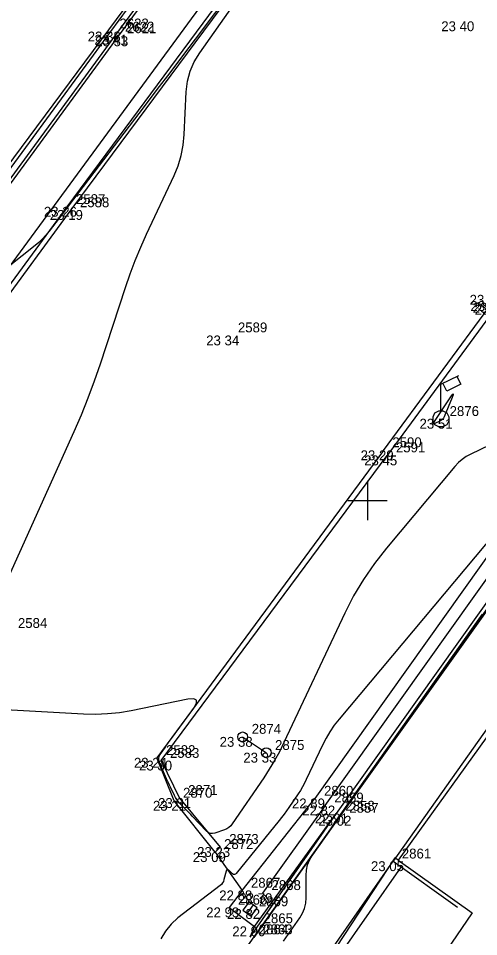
# Model space of a CAD drawing. Extents: x -702257 to -701487, y -1009871 to -1008841.
# Drawn here: x -701883.84 to -701872.19, y -1009561.05 to -1009537.78 of the extents above; entities that cross this region are included whole.
import ezdxf

# ---------------------------------------------------------------- set-up
doc = ezdxf.new("R2010")
doc.units = 0
for name, color, linetype in [('Ex_Major Contours', 7, 'Continuous'), ('Ex_Minor Contours', 7, 'Continuous'), ('Z_body', 7, 'Continuous'), ('Z_body_cisla', 7, 'Continuous'), ('Z_body_vysky_redukovane', 7, 'Continuous'), ('Z_budova', 7, 'Continuous'), ('Z_hektometricka_sit', 7, 'Continuous'), ('Z_katastr_hranice', 7, 'Continuous'), ('Z_katastr_vnitrni_kresba', 7, 'Continuous'), ('Z_komunikace', 7, 'Continuous'), ('Z_nastenka', 7, 'Continuous'), ('Z_obruba', 7, 'Continuous'), ('Z_ploty', 7, 'Continuous'), ('Z_rozhranni', 7, 'Continuous'), ('Z_site_kanalizace_znaky', 7, 'Continuous'), ('Z_site_vo_znaky', 7, 'Continuous'), ('Z_zlabek', 7, 'Continuous')]:
    doc.layers.add(name, color=color, linetype=linetype)

# ---------------------------------------------------------------- blocks, each defined once
blk = doc.blocks.new('POINT_DISPLAY')
blk.add_line((0, 0), (0, 0))
blk = doc.blocks.new('Z46260')
for p, q in [((0.13, 0.13), (-0.13, 0.13)), ((-0.13, 0.13), (-0.13, -0.13)), ((0.13, 0), (-0.13, 0)), ((0.13, -0.13), (0.13, 0.13)), ((-0.13, -0.13), (0.13, -0.13))]:
    blk.add_line(p, q)
blk = doc.blocks.new('Z13')
for p, q in [((0, 0.88), (0.45, 1.1)), ((0.4, 1.07), (0.5, 0.88)), ((0, 0.2), (0, 0.88)), ((0.15, 0.7), (0.05, 0.9)), ((0.5, 0.88), (0.15, 0.7)), ((-0.2, 0.05), (-0.15, 0.15)), ((-0.2, -0.05), (-0.2, 0.05)), ((-0.15, 0.15), (-0.05, 0.2)), ((-0.05, 0.2), (0.05, 0.2)), ((0.05, 0.2), (0.15, 0.15)), ((0.15, 0.15), (0.2, 0.05)), ((0.2, 0.05), (0.2, -0.05)), ((-0.15, -0.15), (-0.2, -0.05)), ((-0.05, -0.2), (-0.15, -0.15)), ((0.05, -0.2), (-0.05, -0.2)), ((0.15, -0.15), (0.05, -0.2)), ((0.2, -0.05), (0.15, -0.15))]:
    blk.add_line(p, q)
blk = doc.blocks.new('Z15')
blk.add_circle((0, 0), 0.125)

msp = doc.modelspace()

# ---------------------------------------------------------------- linework, layer by layer
at = {"layer": 'Ex_Major Contours'}
for points in [[(-701870.663, -1009549.499), (-701875.719, -1009555.543), (-701875.84, -1009555.696), (-701875.949, -1009555.857), (-701876.049, -1009556.024), (-701876.137, -1009556.197), (-701876.549, -1009557.072), (-701876.595, -1009557.165), (-701876.645, -1009557.256), (-701876.698, -1009557.345), (-701876.755, -1009557.432), (-701876.989, -1009557.776), (-701877.049, -1009557.861), (-701877.11, -1009557.945), (-701877.173, -1009558.028), (-701877.237, -1009558.11), (-701878.32, -1009559.451), (-701878.341, -1009559.471), (-701878.364, -1009559.479), (-701878.388, -1009559.475), (-701878.413, -1009559.459), (-701878.514, -1009559.37), (-701878.537, -1009559.355), (-701878.556, -1009559.353), (-701878.57, -1009559.365), (-701878.581, -1009559.391), (-701878.634, -1009559.605), (-701878.649, -1009559.649), (-701878.671, -1009559.689), (-701878.699, -1009559.725), (-701878.733, -1009559.756), (-701879.799, -1009560.575), (-701879.974, -1009560.732), (-701880.117, -1009560.91), (-701880.229, -1009561.109)], [(-701877.124, -1009561.168), (-701876.711, -1009560.577), (-701876.641, -1009560.458), (-701876.591, -1009560.334), (-701876.561, -1009560.203), (-701876.552, -1009560.065), (-701876.555, -1009559.503), (-701876.545, -1009559.366), (-701876.516, -1009559.234), (-701876.466, -1009559.109), (-701876.397, -1009558.991), (-701875.914, -1009558.29), (-701875.807, -1009558.135), (-701875.699, -1009557.98), (-701875.591, -1009557.825), (-701875.482, -1009557.671), (-701872.359, -1009553.263), (-701872.088, -1009552.88)]]:
    msp.add_lwpolyline(points, dxfattribs=at)
at = {"layer": 'Ex_Minor Contours'}
for points in [[(-701876.868, -1009534.981), (-701879.364, -1009538.308), (-701879.685, -1009538.736), (-701880.007, -1009539.163), (-701880.33, -1009539.59), (-701880.653, -1009540.016), (-701882.44, -1009542.368), (-701882.517, -1009542.47), (-701882.594, -1009542.571), (-701882.672, -1009542.673), (-701882.75, -1009542.774), (-701883.06, -1009543.18), (-701883.141, -1009543.279), (-701883.227, -1009543.372), (-701883.318, -1009543.46), (-701883.416, -1009543.542), (-701887.002, -1009546.389)], [(-701884.461, -1009552.752), (-701882.426, -1009548.249), (-701882.243, -1009547.827), (-701882.071, -1009547.401), (-701881.91, -1009546.971), (-701881.761, -1009546.535), (-701881.127, -1009544.604), (-701881.008, -1009544.26), (-701880.879, -1009543.92), (-701880.74, -1009543.584), (-701880.591, -1009543.253), (-701879.894, -1009541.767), (-701879.791, -1009541.517), (-701879.714, -1009541.262), (-701879.663, -1009540.999), (-701879.637, -1009540.731), (-701879.586, -1009539.644), (-701879.555, -1009539.378), (-701879.488, -1009539.125), (-701879.386, -1009538.884), (-701879.247, -1009538.655), (-701876.646, -1009534.956)], [(-701871.913, -1009548.602), (-701872.384, -1009548.824), (-701872.498, -1009548.886), (-701872.603, -1009548.958), (-701872.699, -1009549.041), (-701872.787, -1009549.135), (-701874.52, -1009551.207), (-701874.824, -1009551.594), (-701875.1, -1009551.998), (-701875.35, -1009552.419), (-701875.574, -1009552.857), (-701877.117, -1009556.135), (-701877.231, -1009556.366), (-701877.354, -1009556.591), (-701877.486, -1009556.811), (-701877.626, -1009557.026), (-701878.423, -1009558.195), (-701878.463, -1009558.244), (-701878.508, -1009558.286), (-701878.561, -1009558.319), (-701878.619, -1009558.344), (-701878.865, -1009558.428), (-701878.924, -1009558.44), (-701878.979, -1009558.436), (-701879.03, -1009558.414), (-701879.077, -1009558.376), (-701879.435, -1009557.998), (-701879.475, -1009557.956), (-701879.515, -1009557.914), (-701879.555, -1009557.872), (-701879.595, -1009557.831), (-701879.757, -1009557.665), (-701879.796, -1009557.622), (-701879.83, -1009557.576), (-701879.861, -1009557.528), (-701879.887, -1009557.477), (-701879.987, -1009557.263), (-701880.012, -1009557.21), (-701880.036, -1009557.156), (-701880.06, -1009557.103), (-701880.084, -1009557.049), (-701880.266, -1009556.636), (-701880.282, -1009556.585), (-701880.284, -1009556.534), (-701880.272, -1009556.485), (-701880.247, -1009556.438), (-701880.117, -1009556.249), (-701880.085, -1009556.202), (-701880.052, -1009556.156), (-701880.019, -1009556.109), (-701879.985, -1009556.063), (-701879.4, -1009555.26), (-701879.327, -1009555.134), (-701879.327, -1009555.055), (-701879.399, -1009555.022), (-701879.544, -1009555.035), (-701880.981, -1009555.326), (-701881.281, -1009555.376), (-701881.583, -1009555.408), (-701881.886, -1009555.42), (-701882.191, -1009555.413), (-701885.081, -1009555.252)]]:
    msp.add_lwpolyline(points, dxfattribs=at)
msp.add_lwpolyline([(-701873.072, -1009547.913), (-701873.094, -1009547.942), (-701873.122, -1009547.966), (-701873.154, -1009547.985), (-701873.296, -1009548.052), (-701873.324, -1009548.062), (-701873.338, -1009548.06), (-701873.338, -1009548.046), (-701873.323, -1009548.02), (-701872.892, -1009547.375), (-701872.848, -1009547.313), (-701872.827, -1009547.296), (-701872.83, -1009547.323), (-701872.856, -1009547.394), (-701873.054, -1009547.879)], close=True, dxfattribs=at)
at = {"layer": 'Z_budova'}
for p, q in [((-701881.5, -1009538.12), (-701875.8, -1009530.32)), ((-701887.24, -1009545.95), (-701881.5, -1009538.12)), ((-701868.09, -1009550.27), (-701874.35, -1009559.14)), ((-701874.35, -1009559.14), (-701872.72, -1009560.3))]:
    msp.add_line(p, q, dxfattribs=at)
at = {"layer": 'Z_hektometricka_sit'}
for p, q in [((-701875, -1009549.5), (-701875, -1009550.5)), ((-701875, -1009549.5), (-701875, -1009550.5)), ((-701875.5, -1009550), (-701874.5, -1009550)), ((-701875.5, -1009550), (-701874.5, -1009550))]:
    msp.add_line(p, q, dxfattribs=at)
at = {"layer": 'Z_katastr_hranice'}
for p, q in [((-701769.49, -1009408.19), (-701878.35, -1009561.73)), ((-701896.65, -1009558.4), (-701851.96, -1009498.25)), ((-701895.22, -1009559.28), (-701850.93, -1009498.91)), ((-701871.2, -1009554.9), (-701874.22, -1009559.11)), ((-701874.31, -1009559.05), (-701876.22, -1009561.97)), ((-701874.22, -1009559.11), (-701874.31, -1009559.05))]:
    msp.add_line(p, q, dxfattribs=at)
at = {"layer": 'Z_katastr_vnitrni_kresba'}
for p, q in [((-701874.22, -1009559.11), (-701872.35, -1009560.45)), ((-701872.35, -1009560.45), (-701875.26, -1009564.68))]:
    msp.add_line(p, q, dxfattribs=at)
at = {"layer": 'Z_komunikace'}
for p, q in [((-701882.5, -1009542.64), (-701876.56, -1009534.62)), ((-701887.96, -1009550.06), (-701882.5, -1009542.64)), ((-701874.59, -1009548.73), (-701871.81, -1009544.95)), ((-701874.59, -1009548.73), (-701880.33, -1009556.52)), ((-701879.89, -1009557.61), (-701880.33, -1009556.52)), ((-701878.86, -1009558.91), (-701879.89, -1009557.61)), ((-701878.86, -1009558.91), (-701878.17, -1009559.88)), ((-701877.86, -1009560.79), (-701877.98, -1009561.06))]:
    msp.add_line(p, q, dxfattribs=at)
at = {"layer": 'Z_nastenka'}
msp.add_line((-701878.16, -1009555.99), (-701877.56, -1009556.39), dxfattribs=at)
at = {"layer": 'Z_obruba'}
for p, q in [((-701876.68, -1009534.53), (-701882.61, -1009542.56)), ((-701882.61, -1009542.56), (-701888.06, -1009549.97)), ((-701871.7, -1009545.04), (-701874.5, -1009548.86)), ((-701880.22, -1009556.59), (-701874.5, -1009548.86)), ((-701869.71, -1009549.38), (-701875.79, -1009557.93)), ((-701875.68, -1009557.99), (-701869.61, -1009549.48)), ((-701880.22, -1009556.59), (-701879.76, -1009557.54)), ((-701879.76, -1009557.54), (-701878.73, -1009558.78)), ((-701875.79, -1009557.93), (-701877.98, -1009561.06)), ((-701877.87, -1009561.07), (-701875.68, -1009557.99)), ((-701878.86, -1009558.91), (-701878.73, -1009558.78))]:
    msp.add_line(p, q, dxfattribs=at)
at = {"layer": 'Z_ploty'}
for p, q in [((-701876.39, -1009562.06), (-701874.35, -1009559.14)), ((-701876.15, -1009562.15), (-701874.15, -1009559.29))]:
    msp.add_line(p, q, dxfattribs=at)
at = {"layer": 'Z_rozhranni'}
for p, q in [((-701881.37, -1009538.2), (-701875.66, -1009530.44)), ((-701875.61, -1009530.49), (-701881.31, -1009538.24)), ((-701887.13, -1009546.06), (-701881.37, -1009538.2)), ((-701881.31, -1009538.24), (-701887.07, -1009546.1))]:
    msp.add_line(p, q, dxfattribs=at)
at = {"layer": 'Z_zlabek'}
for p, q in [((-701870.27, -1009549.03), (-701876.33, -1009557.55)), ((-701876.07, -1009557.73), (-701870, -1009549.2)), ((-701878.17, -1009559.88), (-701876.33, -1009557.55)), ((-701876.07, -1009557.73), (-701877.66, -1009559.95)), ((-701877.86, -1009560.79), (-701875.79, -1009557.93)), ((-701878.17, -1009559.88), (-701878.5, -1009560.31)), ((-701878.5, -1009560.31), (-701877.86, -1009560.79))]:
    msp.add_line(p, q, dxfattribs=at)

# ---------------------------------------------------------------- block references
at = {"layer": 'Z_body'}
for p in [(-701872.57, -1009537.86), (-701881.5, -1009538.12), (-701881.37, -1009538.2), (-701881.31, -1009538.24), (-701882.61, -1009542.56), (-701882.5, -1009542.64), (-701878.5, -1009545.82), (-701873.14, -1009547.93), (-701874.59, -1009548.73), (-701874.5, -1009548.86), (-701878.16, -1009555.99), (-701880.33, -1009556.52), (-701877.56, -1009556.39), (-701880.22, -1009556.59), (-701879.89, -1009557.61), (-701879.76, -1009557.54), (-701876.33, -1009557.55), (-701876.07, -1009557.73), (-701875.79, -1009557.93), (-701875.68, -1009557.99), (-701878.73, -1009558.78), (-701878.86, -1009558.91), (-701874.35, -1009559.14), (-701878.17, -1009559.88), (-701877.66, -1009559.95), (-701878.5, -1009560.31), (-701877.97, -1009560.35), (-701877.86, -1009560.79)]:
    msp.add_blockref('POINT_DISPLAY', p, dxfattribs=at)
at = {"layer": 'Z_nastenka'}
for p in [(-701878.16, -1009555.99), (-701877.56, -1009556.39)]:
    msp.add_blockref('Z15', p, dxfattribs=at)
at = {"layer": 'Z_site_kanalizace_znaky', "rotation": 54}
msp.add_blockref('Z46260', (-701877.97, -1009560.35), dxfattribs=at)
at = {"layer": 'Z_site_vo_znaky'}
msp.add_blockref('Z13', (-701873.14, -1009547.93), dxfattribs=at)

# ---------------------------------------------------------------- texts
at = {"layer": 'Z_body_cisla'}
for s, p in [('2623', (-701881.28, -1009538.04)), ('2622', (-701881.14, -1009538.12)), ('2621', (-701881.09, -1009538.16)), ('2587', (-701882.38, -1009542.49)), ('2588', (-701882.28, -1009542.57)), ('2589', (-701878.28, -1009545.74)), ('2876', (-701872.92, -1009547.86)), ('2590', (-701874.37, -1009548.65)), ('2591', (-701874.28, -1009548.78)), ('2584', (-701883.85, -1009553.23)), ('2874', (-701877.93, -1009555.91)), ('2582', (-701880.1, -1009556.45)), ('2583', (-701880, -1009556.52)), ('2875', (-701877.34, -1009556.32)), ('2871', (-701879.54, -1009557.46)), ('2870', (-701879.67, -1009557.53)), ('2860', (-701876.1, -1009557.48)), ('2859', (-701875.84, -1009557.65)), ('2858', (-701875.56, -1009557.86)), ('2857', (-701875.46, -1009557.91)), ('2872', (-701878.63, -1009558.83)), ('2873', (-701878.5, -1009558.7)), ('2861', (-701874.13, -1009559.07)), ('2867', (-701877.95, -1009559.81)), ('2868', (-701877.43, -1009559.87)), ('2866', (-701878.28, -1009560.24)), ('2869', (-701877.75, -1009560.28)), ('2865', (-701877.63, -1009560.71)), ('2864', (-701877.75, -1009560.99)), ('2863', (-701877.64, -1009560.99))]:
    msp.add_text(s, height=0.25, dxfattribs=at).set_placement(p)
at = {"layer": 'Z_body_vysky_redukovane'}
for s, p in [('23 40', (-701873.132, -1009538.11)), ('23 38', (-701882.083, -1009538.37)), ('23 41', (-701881.912, -1009538.45)), ('23 33', (-701881.893, -1009538.49)), ('23 26', (-701883.193, -1009542.81)), ('23 19', (-701883.042, -1009542.89)), ('23 32', (-701872.413, -1009545.04)), ('23 32', (-701872.393, -1009545.2)), ('23 47', (-701872.333, -1009545.24)), ('23 47', (-701872.283, -1009545.29)), ('23 34', (-701879.083, -1009546.07)), ('23 51', (-701873.682, -1009548.18)), ('23 29', (-701875.173, -1009548.98)), ('23 45', (-701875.083, -1009549.11)), ('23 38', (-701878.743, -1009556.24)), ('23 24', (-701880.913, -1009556.77)), ('23 33', (-701878.143, -1009556.64)), ('23 30', (-701880.783, -1009556.84)), ('23 21', (-701880.432, -1009557.86)), ('23 31', (-701880.302, -1009557.79)), ('22 89', (-701876.913, -1009557.8)), ('22 82', (-701876.653, -1009557.98)), ('22 91', (-701876.332, -1009558.18)), ('23 02', (-701876.243, -1009558.24)), ('23 23', (-701879.313, -1009559.03)), ('23 09', (-701879.422, -1009559.16)), ('23 05', (-701874.912, -1009559.39)), ('22 88', (-701878.753, -1009560.13)), ('22 79', (-701878.243, -1009560.2)), ('22 93', (-701879.083, -1009560.56)), ('22 82', (-701878.553, -1009560.6)), ('22 90', (-701878.422, -1009561.04))]:
    msp.add_text(s, height=0.25, dxfattribs=at).set_placement(p)

doc.saveas('drawing.dxf')
